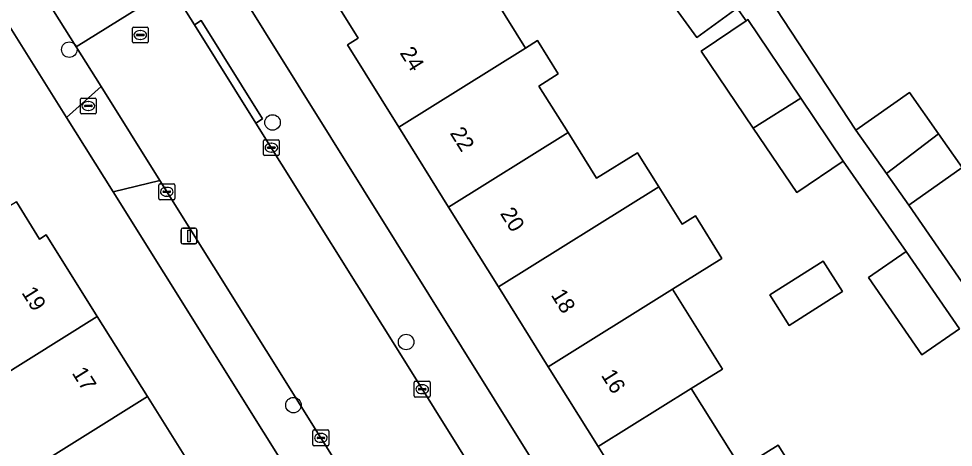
# Model space of a CAD drawing. Extents: x 159664 to 160323, y 385312 to 386115.
# Drawn here: x 160147.9 to 160206.9, y 385760.4 to 385787.5 of the extents above; entities that cross this region are included whole.
import ezdxf

# ---------------------------------------------------------------- set-up
doc = ezdxf.new("R2010")
doc.units = 0
for name, color, linetype in [('IMGEO_Boom', 7, 'Continuous'), ('IMGEO_Brandkraan', 7, 'Continuous'), ('IMGEO_Erf', 7, 'Continuous'), ('IMGEO_Kolk', 7, 'Continuous'), ('IMGEO_Lichtmast', 7, 'Continuous'), ('IMGEO_Pand', 7, 'Continuous'), ('IMGEO_Pand_nummerreeks', 7, 'Continuous'), ('IMGEO_Rijbaan_lokaal_open', 7, 'Continuous'), ('IMGEO_Rioolput', 7, 'Continuous'), ('IMGEO_Voetpad_open', 7, 'Continuous')]:
    doc.layers.add(name, color=color, linetype=linetype)

msp = doc.modelspace()

# ---------------------------------------------------------------- linework, layer by layer
at = {"layer": 'IMGEO_Boom'}
for centre in [(160151.056, 385785.497), (160163.902, 385780.895), (160172.342, 385767.014), (160165.222, 385763.025)]:
    msp.add_circle(centre, 0.489, dxfattribs=at)
at = {"layer": 'IMGEO_Brandkraan'}
for p, q in [((160151.758, 385781.511), (160151.758, 385782.363)), ((160151.833, 385782.437), (160152.685, 385782.437)), ((160152.246, 385782.217), (160152.271, 385782.217)), ((160152.759, 385782.363), (160152.759, 385781.511)), ((160152.017, 385781.931), (160152.017, 385781.943)), ((160152.455, 385781.894), (160152.057, 385781.894)), ((160152.06, 385781.98), (160152.458, 385781.98)), ((160152.269, 385781.657), (160152.244, 385781.657)), ((160152.501, 385781.943), (160152.501, 385781.931)), ((160152.685, 385781.437), (160151.833, 385781.437))]:
    msp.add_line(p, q, dxfattribs=at)
for points in [[(160151.758, 385781.511), (160151.758, 385782.363)], [(160151.833, 385782.437), (160152.685, 385782.437)], [(160152.759, 385782.363), (160152.759, 385781.511)], [(160152.685, 385781.437), (160151.833, 385781.437)]]:
    msp.add_lwpolyline(points, dxfattribs=at)
for centre, radius, start, end in [((160151.835, 385782.361), 0.0765, 91.55205, 178.44795), ((160151.835, 385782.361), 0.0765, 91.55205, 178.44795), ((160152.683, 385782.361), 0.0765, 1.55205, 88.44795), ((160152.683, 385782.361), 0.0765, 1.55205, 88.44795), ((160152.057, 385781.94), 0.0403, 85.87752, 175.75265), ((160152.054, 385781.93), 0.0366, 178.93798, 274.71019), ((160152.458, 385781.937), 0.043, 264.86636, 352.45326), ((160152.462, 385781.942), 0.0386, 1.73085, 96.63898), ((160151.835, 385781.513), 0.0765, 181.55205, 268.44795), ((160151.835, 385781.513), 0.0765, 181.55205, 268.44795), ((160152.683, 385781.513), 0.0765, 271.55205, 358.44795), ((160152.683, 385781.513), 0.0765, 271.55205, 358.44795)]:
    msp.add_arc(centre, radius, start, end, dxfattribs=at)
for centre, major_axis, ratio, start_param, end_param in [((160152.245, 385781.937), (-0.387, 0.002), 0.722429, 4.712389, 7.853982), ((160152.27, 385781.937), (-0.39, 0.002), 0.717154, 1.570796, 4.712389)]:
    msp.add_ellipse(centre, major_axis=major_axis, ratio=ratio, start_param=start_param, end_param=end_param, dxfattribs=at)
at = {"layer": 'IMGEO_Erf'}
for points in [[(160115.537, 385863.36), (160186.266, 385750), (160208.863, 385713.863)], [(160147.718, 385775.872), (160149.166, 385773.522), (160149.594, 385773.79), (160152.823, 385768.63), (160155.991, 385763.568), (160159.158, 385758.507), (160162.325, 385753.446), (160164.482, 385750), (160165.493, 385748.384), (160168.661, 385743.322), (160171.828, 385738.262), (160174.996, 385733.199), (160178.164, 385728.137), (160181.388, 385722.986), (160185.641, 385725.647), (160153.829, 385776.507), (160150.881, 385781.215), (160119.147, 385831.981)], [(160176.718, 385790.692), (160179.897, 385785.599), (160180.648, 385786.067), (160181.963, 385783.96), (160180.739, 385783.197), (160182.575, 385780.256), (160184.377, 385777.369), (160186.963, 385778.983), (160188.312, 385776.822), (160189.781, 385774.469), (160190.623, 385774.995), (160192.304, 385772.301), (160189.177, 385770.349), (160192.328, 385765.302), (160190.365, 385764.077), (160193.516, 385759.029), (160195.866, 385760.496), (160199.016, 385755.449)], [(160207.315, 385767.854), (160204.933, 385766.207), (160201.558, 385771.089), (160203.94, 385772.736), (160199.956, 385778.452), (160197.028, 385776.47), (160194.272, 385780.543), (160190.986, 385785.398), (160193.825, 385787.32), (160193.275, 385788.112), (160190.714, 385786.265), (160187.687, 385790.462)], [(160195.294, 385788.767), (160200.775, 385780.416), (160204.149, 385782.79), (160205.993, 385780.169), (160207.491, 385778.041), (160204.116, 385775.667), (160209.976, 385767.17)], [(160208.08, 385722.432), (160204.849, 385727.653), (160201.616, 385732.876), (160200.316, 385735.036), (160197.084, 385740.214), (160193.933, 385745.262), (160190.975, 385750), (160190.783, 385750.308), (160187.632, 385755.356), (160184.481, 385760.404), (160181.33, 385765.451), (160178.18, 385770.497), (160175.029, 385775.545), (160171.878, 385780.593), (160168.629, 385785.798), (160169.308, 385786.221), (160167.875, 385788.517)]]:
    msp.add_lwpolyline(points, dxfattribs=at)
msp.add_lwpolyline([(160198.701, 385772.121), (160199.916, 385770.2), (160196.543, 385768.068), (160195.329, 385769.989)], close=True, dxfattribs=at)
at = {"layer": 'IMGEO_Kolk'}
for p, q in [((160163.326, 385778.874), (160163.326, 385779.726)), ((160163.401, 385779.8), (160164.253, 385779.8)), ((160163.585, 385779.294), (160163.585, 385779.306)), ((160164.023, 385779.257), (160163.625, 385779.257)), ((160163.628, 385779.343), (160164.026, 385779.343)), ((160163.814, 385779.58), (160163.839, 385779.58)), ((160164.069, 385779.306), (160164.069, 385779.294)), ((160164.327, 385779.726), (160164.327, 385778.874)), ((160164.253, 385778.8), (160163.401, 385778.8)), ((160163.837, 385779.02), (160163.812, 385779.02)), ((160156.718, 385776.086), (160156.718, 385776.938)), ((160156.793, 385777.012), (160157.645, 385777.012)), ((160157.719, 385776.938), (160157.719, 385776.086)), ((160156.977, 385776.506), (160156.977, 385776.518)), ((160157.415, 385776.469), (160157.017, 385776.469)), ((160157.02, 385776.555), (160157.418, 385776.555)), ((160157.206, 385776.792), (160157.231, 385776.792)), ((160157.461, 385776.518), (160157.461, 385776.506)), ((160157.645, 385776.012), (160156.793, 385776.012)), ((160157.229, 385776.232), (160157.204, 385776.232)), ((160172.86, 385763.605), (160172.86, 385764.457)), ((160172.935, 385764.531), (160173.787, 385764.531)), ((160173.861, 385764.457), (160173.861, 385763.605)), ((160173.119, 385764.025), (160173.119, 385764.037)), ((160173.557, 385763.988), (160173.159, 385763.988)), ((160173.162, 385764.074), (160173.56, 385764.074)), ((160173.348, 385764.311), (160173.373, 385764.311)), ((160173.603, 385764.037), (160173.603, 385764.025)), ((160173.787, 385763.531), (160172.935, 385763.531)), ((160173.371, 385763.751), (160173.346, 385763.751)), ((160166.454, 385760.527), (160166.454, 385761.379)), ((160166.529, 385761.453), (160167.381, 385761.453)), ((160166.713, 385760.947), (160166.713, 385760.959)), ((160167.151, 385760.91), (160166.753, 385760.91)), ((160166.756, 385760.996), (160167.154, 385760.996)), ((160166.942, 385761.233), (160166.967, 385761.233)), ((160167.197, 385760.959), (160167.197, 385760.947)), ((160167.455, 385761.379), (160167.455, 385760.527)), ((160167.381, 385760.453), (160166.529, 385760.453)), ((160166.965, 385760.673), (160166.94, 385760.673))]:
    msp.add_line(p, q, dxfattribs=at)
for points in [[(160163.326, 385778.874), (160163.326, 385779.726)], [(160163.401, 385779.8), (160164.253, 385779.8)], [(160164.327, 385779.726), (160164.327, 385778.874)], [(160164.253, 385778.8), (160163.401, 385778.8)], [(160156.718, 385776.086), (160156.718, 385776.938)], [(160156.793, 385777.012), (160157.645, 385777.012)], [(160157.719, 385776.938), (160157.719, 385776.086)], [(160157.645, 385776.012), (160156.793, 385776.012)], [(160172.86, 385763.605), (160172.86, 385764.457)], [(160172.935, 385764.531), (160173.787, 385764.531)], [(160173.861, 385764.457), (160173.861, 385763.605)], [(160173.787, 385763.531), (160172.935, 385763.531)], [(160166.454, 385760.527), (160166.454, 385761.379)], [(160166.529, 385761.453), (160167.381, 385761.453)], [(160167.455, 385761.379), (160167.455, 385760.527)], [(160167.381, 385760.453), (160166.529, 385760.453)]]:
    msp.add_lwpolyline(points, dxfattribs=at)
for centre, radius, start, end in [((160163.403, 385779.724), 0.0765, 91.55205, 178.44795), ((160163.403, 385779.724), 0.0765, 91.55205, 178.44795), ((160163.625, 385779.303), 0.0403, 85.87752, 175.75265), ((160163.622, 385779.293), 0.0366, 178.93798, 274.71019), ((160164.026, 385779.3), 0.043, 264.86636, 352.45326), ((160164.03, 385779.305), 0.0386, 1.73085, 96.63898), ((160164.251, 385779.724), 0.0765, 1.55205, 88.44795), ((160164.251, 385779.724), 0.0765, 1.55205, 88.44795), ((160163.403, 385778.876), 0.0765, 181.55205, 268.44795), ((160163.403, 385778.876), 0.0765, 181.55205, 268.44795), ((160164.251, 385778.876), 0.0765, 271.55205, 358.44795), ((160164.251, 385778.876), 0.0765, 271.55205, 358.44795), ((160156.795, 385776.936), 0.0765, 91.55205, 178.44795), ((160156.795, 385776.936), 0.0765, 91.55205, 178.44795), ((160157.643, 385776.936), 0.0765, 1.55205, 88.44795), ((160157.643, 385776.936), 0.0765, 1.55205, 88.44795), ((160157.017, 385776.515), 0.0403, 85.87752, 175.75265), ((160157.014, 385776.505), 0.0366, 178.93798, 274.71019), ((160157.418, 385776.512), 0.043, 264.86636, 352.45326), ((160157.422, 385776.517), 0.0386, 1.73085, 96.63898), ((160156.795, 385776.088), 0.0765, 181.55205, 268.44795), ((160156.795, 385776.088), 0.0765, 181.55205, 268.44795), ((160157.643, 385776.088), 0.0765, 271.55205, 358.44795), ((160157.643, 385776.088), 0.0765, 271.55205, 358.44795), ((160172.937, 385764.455), 0.0765, 91.55205, 178.44795), ((160172.937, 385764.455), 0.0765, 91.55205, 178.44795), ((160173.785, 385764.455), 0.0765, 1.55205, 88.44795), ((160173.785, 385764.455), 0.0765, 1.55205, 88.44795), ((160173.159, 385764.034), 0.0403, 85.87752, 175.75265), ((160173.156, 385764.024), 0.0366, 178.93798, 274.71019), ((160173.56, 385764.031), 0.043, 264.86636, 352.45326), ((160173.564, 385764.036), 0.0386, 1.73085, 96.63898), ((160172.937, 385763.607), 0.0765, 181.55205, 268.44795), ((160172.937, 385763.607), 0.0765, 181.55205, 268.44795), ((160173.785, 385763.607), 0.0765, 271.55205, 358.44795), ((160173.785, 385763.607), 0.0765, 271.55205, 358.44795), ((160166.531, 385761.377), 0.0765, 91.55205, 178.44795), ((160166.531, 385761.377), 0.0765, 91.55205, 178.44795), ((160166.753, 385760.956), 0.0403, 85.87752, 175.75265), ((160166.75, 385760.946), 0.0366, 178.93798, 274.71019), ((160167.154, 385760.953), 0.043, 264.86636, 352.45326), ((160167.158, 385760.958), 0.0386, 1.73085, 96.63898), ((160167.379, 385761.377), 0.0765, 1.55205, 88.44795), ((160167.379, 385761.377), 0.0765, 1.55205, 88.44795), ((160166.531, 385760.529), 0.0765, 181.55205, 268.44795), ((160166.531, 385760.529), 0.0765, 181.55205, 268.44795), ((160167.379, 385760.529), 0.0765, 271.55205, 358.44795), ((160167.379, 385760.529), 0.0765, 271.55205, 358.44795)]:
    msp.add_arc(centre, radius, start, end, dxfattribs=at)
for centre, major_axis, ratio, start_param, end_param in [((160163.813, 385779.3), (-0.387, 0.002), 0.722429, 4.712389, 7.853982), ((160163.838, 385779.3), (-0.39, 0.002), 0.717154, 1.570796, 4.712389), ((160157.205, 385776.512), (-0.387, 0.002), 0.722429, 4.712389, 7.853982), ((160157.23, 385776.512), (-0.39, 0.002), 0.717154, 1.570796, 4.712389), ((160173.347, 385764.031), (-0.387, 0.002), 0.722429, 4.712389, 7.853982), ((160173.372, 385764.031), (-0.39, 0.002), 0.717154, 1.570796, 4.712389), ((160166.941, 385760.953), (-0.387, 0.002), 0.722429, 4.712389, 7.853982), ((160166.966, 385760.953), (-0.39, 0.002), 0.717154, 1.570796, 4.712389)]:
    msp.add_ellipse(centre, major_axis=major_axis, ratio=ratio, start_param=start_param, end_param=end_param, dxfattribs=at)
at = {"layer": 'IMGEO_Lichtmast'}
for p, q in [((160158.123, 385773.312), (160158.123, 385774.112)), ((160158.123, 385774.112), (160158.123, 385773.312)), ((160158.223, 385774.212), (160159.013, 385774.212)), ((160159.013, 385774.212), (160158.223, 385774.212)), ((160159.113, 385774.112), (160159.113, 385773.312)), ((160159.113, 385773.312), (160159.113, 385774.112)), ((160159.013, 385773.212), (160158.223, 385773.212)), ((160158.223, 385773.212), (160159.013, 385773.212))]:
    msp.add_line(p, q, dxfattribs=at)
msp.add_lwpolyline([(160158.543, 385774.087), (160158.693, 385774.087), (160158.693, 385773.337), (160158.543, 385773.337), (160158.543, 385774.087)], dxfattribs=at)
for centre, start, end in [((160158.223, 385774.112), 90, 180), ((160158.223, 385774.112), 90, 180), ((160159.013, 385774.112), 0, 90), ((160159.013, 385774.112), 360, 90), ((160158.223, 385773.312), 180, 270), ((160158.223, 385773.312), 180, 270), ((160159.013, 385773.312), 270, 0), ((160159.013, 385773.312), 270, 0)]:
    msp.add_arc(centre, 0.1, start, end, dxfattribs=at)
at = {"layer": 'IMGEO_Pand'}
for points in [[(160169.308, 385786.221), (160168.629, 385785.798), (160171.878, 385780.593), (160179.897, 385785.599), (160176.718, 385790.692), (160175.215, 385793.099), (160167.875, 385788.517)], [(160190.777, 385792.391), (160187.687, 385790.462), (160190.714, 385786.265), (160193.275, 385788.112), (160193.661, 385788.39)], [(160193.825, 385787.32), (160190.986, 385785.398), (160194.272, 385780.543), (160197.297, 385782.433), (160193.939, 385787.397)], [(160182.575, 385780.256), (160180.739, 385783.197), (160181.963, 385783.96), (160180.648, 385786.067), (160179.897, 385785.599), (160171.878, 385780.593), (160175.029, 385775.545)], [(160200.775, 385780.416), (160202.705, 385777.673), (160205.993, 385780.169), (160204.149, 385782.79)], [(160197.297, 385782.433), (160194.272, 385780.543), (160197.028, 385776.47), (160199.956, 385778.452)], [(160175.029, 385775.545), (160178.18, 385770.497), (160188.312, 385776.822), (160186.963, 385778.983), (160184.377, 385777.369), (160182.575, 385780.256)], [(160205.993, 385780.169), (160202.705, 385777.673), (160204.116, 385775.667), (160207.491, 385778.041)], [(160189.781, 385774.469), (160188.312, 385776.822), (160178.18, 385770.497), (160181.33, 385765.451), (160189.177, 385770.349), (160192.304, 385772.301), (160190.623, 385774.995)], [(160144.286, 385763.291), (160152.823, 385768.63), (160149.594, 385773.79), (160149.166, 385773.522), (160147.718, 385775.872), (160142.319, 385772.537), (160139.46, 385770.783), (160143.037, 385765.291)], [(160203.94, 385772.736), (160201.558, 385771.089), (160204.933, 385766.207), (160207.315, 385767.854)], [(160199.916, 385770.2), (160198.701, 385772.121), (160195.329, 385769.989), (160196.543, 385768.068)], [(160181.33, 385765.451), (160184.481, 385760.404), (160190.365, 385764.077), (160192.328, 385765.302), (160189.177, 385770.349)], [(160155.991, 385763.568), (160152.823, 385768.63), (160144.286, 385763.291), (160147.449, 385758.224)], [(160193.516, 385759.029), (160190.365, 385764.077), (160184.481, 385760.404), (160187.632, 385755.356)], [(160147.449, 385758.224), (160150.61, 385753.16), (160159.158, 385758.507), (160155.991, 385763.568)], [(160195.866, 385760.496), (160193.516, 385759.029), (160187.632, 385755.356), (160190.783, 385750.308), (160199.016, 385755.449)]]:
    msp.add_lwpolyline(points, close=True, dxfattribs=at)
at = {"layer": 'IMGEO_Rijbaan_lokaal_open'}
for points in [[(160157.501, 385789.431), (160156.071, 385791.721), (160150.057, 385787.961), (160151.489, 385785.672)], [(160157.501, 385789.431), (160151.489, 385785.672), (160153.063, 385783.158), (160156.775, 385777.224), (160166.919, 385761.012), (160173.837, 385750), (160183.468, 385734.67), (160189.384, 385738.386), (160182.127, 385750), (160172.467, 385765.461), (160162.854, 385780.857), (160158.977, 385787.068)]]:
    msp.add_lwpolyline(points, close=True, dxfattribs=at)
at = {"layer": 'IMGEO_Rioolput'}
for p, q in [((160155.116, 385786.924), (160155.968, 385786.924)), ((160155.041, 385785.998), (160155.041, 385786.85)), ((160155.3, 385786.418), (160155.3, 385786.43)), ((160155.738, 385786.381), (160155.34, 385786.381)), ((160155.343, 385786.467), (160155.741, 385786.467)), ((160155.529, 385786.704), (160155.554, 385786.704)), ((160155.784, 385786.43), (160155.784, 385786.418)), ((160156.042, 385786.85), (160156.042, 385785.998)), ((160155.968, 385785.924), (160155.116, 385785.924)), ((160155.552, 385786.144), (160155.527, 385786.144))]:
    msp.add_line(p, q, dxfattribs=at)
for points in [[(160155.116, 385786.924), (160155.968, 385786.924)], [(160155.041, 385785.998), (160155.041, 385786.85)], [(160156.042, 385786.85), (160156.042, 385785.998)], [(160155.968, 385785.924), (160155.116, 385785.924)]]:
    msp.add_lwpolyline(points, dxfattribs=at)
for centre, radius, start, end in [((160155.118, 385786.848), 0.0765, 91.55205, 178.44795), ((160155.118, 385786.848), 0.0765, 91.55205, 178.44795), ((160155.966, 385786.848), 0.0765, 1.55205, 88.44795), ((160155.966, 385786.848), 0.0765, 1.55205, 88.44795), ((160155.34, 385786.427), 0.0403, 85.87752, 175.75265), ((160155.337, 385786.417), 0.0366, 178.93798, 274.71019), ((160155.741, 385786.424), 0.043, 264.86636, 352.45326), ((160155.745, 385786.429), 0.0386, 1.73085, 96.63898), ((160155.118, 385786), 0.0765, 181.55205, 268.44795), ((160155.118, 385786), 0.0765, 181.55205, 268.44795), ((160155.966, 385786), 0.0765, 271.55205, 358.44795), ((160155.966, 385786), 0.0765, 271.55205, 358.44795)]:
    msp.add_arc(centre, radius, start, end, dxfattribs=at)
for centre, major_axis, ratio, start_param, end_param in [((160155.528, 385786.424), (-0.387, 0.002), 0.722429, 4.712389, 7.853982), ((160155.553, 385786.424), (-0.39, 0.002), 0.717154, 1.570796, 4.712389)]:
    msp.add_ellipse(centre, major_axis=major_axis, ratio=ratio, start_param=start_param, end_param=end_param, dxfattribs=at)
at = {"layer": 'IMGEO_Voetpad_open'}
for points in [[(160208.863, 385713.863), (160186.266, 385750), (160115.537, 385863.36)], [(160104.128, 385856.007), (160118.41, 385833.159), (160119.147, 385831.981), (160150.881, 385781.215), (160153.063, 385783.158), (160151.489, 385785.672), (160150.057, 385787.961), (160143.743, 385798.053), (160134.087, 385813.642), (160123.121, 385831.177), (160121.694, 385833.457), (160106.744, 385857.623)], [(160136.267, 385823.382), (160154.612, 385794.058), (160156.071, 385791.721), (160157.501, 385789.431), (160158.977, 385787.068), (160159.4, 385787.334), (160163.277, 385781.123), (160162.854, 385780.857), (160172.467, 385765.461), (160182.127, 385750), (160189.384, 385738.386), (160190.867, 385736.011), (160193.045, 385732.527), (160193.468, 385732.793), (160195.397, 385729.705), (160194.974, 385729.439), (160201.529, 385719.139), (160201.866, 385719.351), (160203.89, 385716.111), (160203.565, 385715.906), (160204.045, 385715.132), (160205.557, 385712.692), (160205.668, 385712.503)], [(160209.976, 385767.17), (160204.116, 385775.667), (160202.705, 385777.673), (160200.775, 385780.416), (160195.294, 385788.767)], [(160193.275, 385788.112), (160193.825, 385787.32), (160193.939, 385787.397), (160197.297, 385782.433), (160199.956, 385778.452), (160203.94, 385772.736), (160207.315, 385767.854)], [(160190.72, 385723.128), (160190.297, 385722.862), (160188.336, 385725.983), (160188.759, 385726.249), (160184.958, 385732.298), (160183.468, 385734.67), (160173.837, 385750), (160166.919, 385761.012), (160156.775, 385777.224), (160153.829, 385776.507), (160185.641, 385725.647), (160186.316, 385724.569), (160188.207, 385721.545), (160193.089, 385713.731), (160196.11, 385708.897)]]:
    msp.add_lwpolyline(points, dxfattribs=at)
for points in [[(160162.854, 385780.857), (160163.277, 385781.123), (160159.4, 385787.334), (160158.977, 385787.068)], [(160156.775, 385777.224), (160153.063, 385783.158), (160150.881, 385781.215), (160153.829, 385776.507)]]:
    msp.add_lwpolyline(points, close=True, dxfattribs=at)

# ---------------------------------------------------------------- texts
at = {"layer": 'IMGEO_Pand_nummerreeks'}
for s, rotation, p in [('24', 301.97351, (160171.913, 385785.295)), ('22', 301.97351, (160175.08, 385780.221)), ('20', 301.97351, (160178.253, 385775.14)), ('19', 302.03882, (160148.012, 385770.135)), ('18', 301.97083, (160181.469, 385769.987)), ('17', 302.03882, (160151.192, 385765.055)), ('16', 301.97351, (160184.636, 385764.913))]:
    msp.add_text(s, height=1, rotation=rotation, dxfattribs=at).set_placement(p)

doc.saveas('drawing.dxf')
